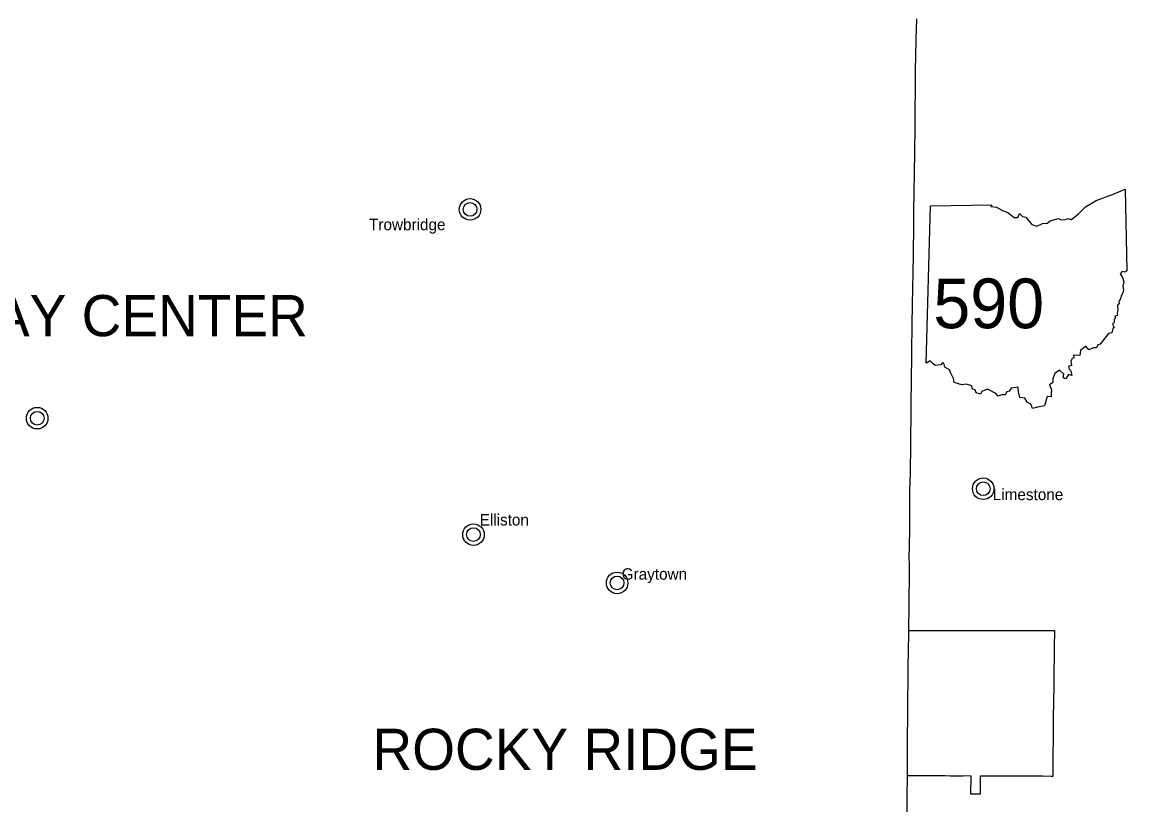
# Model space of a CAD drawing. Extents: x -82 to 873, y 0 to 440.
# Drawn here: x 144.2 to 244.9, y 182.3 to 253.6 of the extents above; entities that cross this region are included whole.
import ezdxf

# ---------------------------------------------------------------- set-up
doc = ezdxf.new("R2010")
doc.units = 0
for name, color, linetype in [('DV_X_Corp_Line', 7, 'Continuous'), ('GM_X_Corporation_Text', 7, 'Continuous'), ('GM_X_Interstate_Route', 7, 'Continuous'), ('PV_P_Text', 7, 'Continuous')]:
    doc.layers.add(name, color=color, linetype=linetype)

msp = doc.modelspace()

# ---------------------------------------------------------------- linework, layer by layer
at = {"layer": 'DV_X_Corp_Line'}
msp.add_lwpolyline([(225.04, 198.2), (226.37, 198.2), (229.03, 198.2), (230.75, 198.2), (231.37, 198.2), (231.68, 198.2), (232.06, 198.2), (233.21, 198.2), (234.89, 198.21), (235.92, 198.2), (236.53, 198.2), (237.14, 198.2), (238.31, 198.21), (238.31, 197.85), (238.3, 196.99), (238.28, 195.43), (238.27, 194.82), (238.26, 193.92), (238.25, 192.81), (238.24, 192.05), (238.23, 191.59), (238.22, 191.41), (238.21, 190.59), (238.2, 189.9), (238.19, 188.67), (238.18, 188.05), (238.17, 187.15), (238.15, 185.51), (238.15, 184.91), (238, 184.91), (237.23, 184.92), (236.53, 184.92), (234.35, 184.92), (232.84, 184.93), (232.22, 184.93), (231.55, 184.94), (231.53, 183.29), (230.69, 183.29), (230.72, 184.94), (230.41, 184.95), (230, 184.94), (229.71, 184.94), (229.26, 184.94), (228.8, 184.94), (228.35, 184.95), (227.12, 184.95), (226.01, 184.95), (224.91, 184.95), (224.91, 185.27), (224.92, 187.15), (224.93, 188.26), (224.93, 188.76), (224.93, 188.88), (224.94, 189.9), (224.94, 190.23), (224.94, 190.68), (224.95, 191.17), (224.95, 191.6), (224.95, 191.95), (224.96, 192.44), (224.97, 193.06), (224.98, 193.63), (224.99, 194.78), (224.99, 195.27), (225, 195.93), (225.02, 196.51), (225.04, 197.78)], close=True, dxfattribs=at)
for centre, radius in [((185.05, 236.58), 0.982), ((185.05, 236.58), 0.623), ((145.59, 217.55), 0.982), ((145.59, 217.55), 0.623), ((231.82, 211.12), 0.982), ((231.82, 211.12), 0.623), ((185.36, 206.94), 0.982), ((185.36, 206.94), 0.623), ((198.45, 202.54), 0.982), ((198.45, 202.54), 0.623)]:
    msp.add_circle(centre, radius, dxfattribs=at)
at = {"layer": 'GM_X_Interstate_Route'}
for points in [[(225.14, 210.28), (225.14, 210.58), (225.14, 211.03), (225.16, 211.69), (225.18, 212.59), (225.19, 213.29), (225.21, 214.4), (225.22, 215.01), (225.23, 215.38), (225.23, 215.75), (225.25, 217.85), (225.26, 218.26), (225.26, 218.96), (225.26, 219.61), (225.27, 220.27), (225.27, 221.21), (225.27, 221.75), (225.28, 221.95), (225.31, 222.36), (225.32, 222.61), (225.32, 223.22), (225.32, 223.72), (225.32, 224.29), (225.33, 225.4), (225.34, 226.18), (225.35, 226.63), (225.36, 227.33), (225.38, 228.07), (225.39, 229.22), (225.41, 229.83), (225.42, 230.37), (225.42, 230.73), (225.44, 231.39), (225.44, 231.43), (225.45, 231.84), (225.45, 232.25), (225.47, 233.16), (225.49, 234.47), (225.5, 235.13), (225.51, 236.11), (225.51, 236.64), (225.53, 238), (225.54, 238.74), (225.55, 239.27), (225.57, 240.34), (225.59, 241.28), (225.59, 241.59), (225.6, 242.6), (225.61, 243.29), (225.61, 243.95), (225.61, 244.65), (225.62, 245.24), (225.62, 245.35), (225.63, 245.84), (225.65, 247.24), (225.65, 248.18), (225.66, 248.75), (225.66, 249.2), (225.66, 249.57), (225.68, 250.31), (225.69, 250.93), (225.71, 251.67), (225.72, 252.24), (225.74, 252.94), (225.77, 253.96)], [(225.04, 198.2), (225.06, 200.39), (225.07, 200.8), (225.08, 201.75), (225.09, 202.33), (225.09, 202.42), (225.09, 203.19), (225.09, 204.34), (225.08, 204.75), (225.1, 205.98), (225.12, 207.37), (225.12, 207.7), (225.13, 208.12), (225.14, 209.52), (225.14, 210.28)], [(224.91, 184.95), (224.91, 185.27), (224.92, 187.15), (224.93, 188.26), (224.93, 188.76), (224.93, 188.88), (224.94, 189.9), (224.94, 190.23), (224.94, 190.68), (224.95, 191.17), (224.95, 191.6), (224.95, 191.95), (224.96, 192.44), (224.97, 193.06), (224.98, 193.63), (224.99, 194.78), (224.99, 195.27), (225, 195.93), (225.02, 196.51), (225.04, 197.78), (225.04, 198.2)], [(224.86, 178.3), (224.87, 178.45), (224.88, 179.15), (224.89, 179.61), (224.88, 180.72), (224.88, 181.09), (224.89, 181.7), (224.9, 182.94), (224.9, 183.63), (224.91, 184.37), (224.91, 184.95)]]:
    msp.add_lwpolyline(points, dxfattribs=at)
at = {"layer": 'PV_P_Text'}
msp.add_line((226.61, 222.55), (227.01, 236.91), dxfattribs=at)
msp.add_line((226.61, 222.55), (227.01, 236.91), dxfattribs=at)
for points in [[(227.01, 236.91), (232.59, 237), (232.5, 236.83), (233.03, 236.79), (233.59, 236.49), (234.06, 236.29), (234.64, 235.84), (234.98, 235.84), (235.13, 236.22), (235.39, 235.93), (235.71, 235.88), (236.25, 235.19), (236.7, 235.04), (237.23, 235.28), (237.64, 235.31), (237.93, 235.55), (238.69, 235.75), (238.91, 235.63), (239.31, 235.65), (239.52, 235.74), (239.87, 235.66), (240.49, 236.18), (241.13, 236.8), (242.11, 237.38), (243.59, 237.93), (244.75, 238.42), (244.92, 230.97)], [(227.01, 236.91), (232.59, 237), (232.5, 236.83), (233.03, 236.79), (233.59, 236.49), (234.06, 236.29), (234.64, 235.84), (234.98, 235.84), (235.13, 236.22), (235.39, 235.93), (235.71, 235.88), (236.25, 235.19), (236.7, 235.04), (237.23, 235.28), (237.64, 235.31), (237.93, 235.55), (238.69, 235.75), (238.91, 235.63), (239.31, 235.65), (239.52, 235.74), (239.87, 235.66), (240.49, 236.18), (241.13, 236.8), (242.11, 237.38), (243.59, 237.93), (244.75, 238.42), (244.92, 230.97)], [(244.92, 230.97), (244.74, 230.86), (244.48, 230.91), (244.3, 230.7), (244.52, 230.36), (244.63, 229.99), (244.53, 229.58), (244.62, 229.25), (244.56, 228.97), (244.39, 228.69), (244.34, 228.42), (244.19, 228.14), (244.21, 227.98), (244.07, 227.86), (244.09, 227.39), (244.02, 227.14), (244.05, 226.91), (243.83, 226.85), (243.88, 226.67), (243.74, 226.53), (243.77, 226.28), (243.61, 226.13), (243.76, 225.81), (243.64, 225.71), (243.54, 225.33), (243.25, 225.26), (242.69, 224.56), (242.49, 224.3), (242.26, 224.23), (242.14, 223.96), (241.86, 223.96), (241.44, 223.78), (241.17, 224.1), (240.7, 223.71), (240.64, 223.26), (240.04, 223.28), (240.07, 223.05), (239.93, 222.98), (239.81, 222.76), (239.88, 222.35), (239.6, 222.25), (239.64, 222.02), (239.82, 221.87), (239.9, 221.43), (239.6, 221.52), (239.35, 221.14), (239.1, 221.23), (239.18, 221.55), (238.76, 221.93), (238.36, 221.62), (238.15, 221.13), (238.15, 220.8), (237.85, 220.6), (238.04, 220.14), (238, 219.81), (238.01, 219.51), (237.64, 219.52), (237.41, 218.69)], [(244.92, 230.97), (244.74, 230.86), (244.48, 230.91), (244.3, 230.7), (244.52, 230.36), (244.63, 229.99), (244.53, 229.58), (244.62, 229.25), (244.56, 228.97), (244.39, 228.69), (244.34, 228.42), (244.19, 228.14), (244.21, 227.98), (244.07, 227.86), (244.09, 227.39), (244.02, 227.14), (244.05, 226.91), (243.83, 226.85), (243.88, 226.67), (243.74, 226.53), (243.77, 226.28), (243.61, 226.13), (243.76, 225.81), (243.64, 225.71), (243.54, 225.33), (243.25, 225.26), (242.69, 224.56), (242.49, 224.3), (242.26, 224.23), (242.14, 223.96), (241.86, 223.96), (241.44, 223.78), (241.17, 224.1), (240.7, 223.71), (240.64, 223.26), (240.04, 223.28), (240.07, 223.05), (239.93, 222.98), (239.81, 222.76), (239.88, 222.35), (239.6, 222.25), (239.64, 222.02), (239.82, 221.87), (239.9, 221.43), (239.6, 221.52), (239.35, 221.14), (239.1, 221.23), (239.18, 221.55), (238.76, 221.93), (238.36, 221.62), (238.15, 221.13), (238.15, 220.8), (237.85, 220.6), (238.04, 220.14), (238, 219.81), (238.01, 219.51), (237.64, 219.52), (237.41, 218.69)], [(237.41, 218.69), (236.76, 218.54), (236.31, 218.44), (236.15, 218.82), (235.83, 219.01), (235.62, 219.39), (235.15, 219.44), (235.04, 219.96), (234.99, 220.38), (234.36, 220.28), (234.18, 220.02), (233.96, 219.95), (233.83, 219.69), (233.52, 219.67), (233.19, 219.55), (232.98, 219.8), (232.44, 220.06), (232.2, 220.19), (231.69, 219.98), (231.58, 219.74), (231.18, 219.85), (231.08, 220.12), (230.84, 220.2), (230.79, 220.49), (230.26, 220.64), (229.87, 220.58), (229.16, 220.81), (229.12, 221.18), (228.88, 221.64), (228.75, 221.96), (228.31, 222.2), (228.22, 222.58), (228.08, 222.57), (227.95, 222.42), (227.45, 222.35), (227.26, 222.5), (226.98, 222.77), (226.61, 222.55)], [(237.41, 218.69), (236.76, 218.54), (236.31, 218.44), (236.15, 218.82), (235.83, 219.01), (235.62, 219.39), (235.15, 219.44), (235.04, 219.96), (234.99, 220.38), (234.36, 220.28), (234.18, 220.02), (233.96, 219.95), (233.83, 219.69), (233.52, 219.67), (233.19, 219.55), (232.98, 219.8), (232.44, 220.06), (232.2, 220.19), (231.69, 219.98), (231.58, 219.74), (231.18, 219.85), (231.08, 220.12), (230.84, 220.2), (230.79, 220.49), (230.26, 220.64), (229.87, 220.58), (229.16, 220.81), (229.12, 221.18), (228.88, 221.64), (228.75, 221.96), (228.31, 222.2), (228.22, 222.58), (228.08, 222.57), (227.95, 222.42), (227.45, 222.35), (227.26, 222.5), (226.98, 222.77), (226.61, 222.55)]]:
    msp.add_lwpolyline(points, dxfattribs=at)

# ---------------------------------------------------------------- texts
at = {"layer": 'DV_X_Corp_Line'}
for s, p in [('Trowbridge', (175.84, 234.68)), ('Limestone', (232.69, 210.08)), ('Elliston', (185.92, 207.77)), ('Graytown', (198.87, 202.83))]:
    msp.add_text(s, height=1.042, rotation=0.005, dxfattribs=at).set_placement(p)
at = {"layer": 'GM_X_Corporation_Text'}
for s, p in [('CLAY CENTER', (135.15, 225.02)), ('ROCKY RIDGE', (176.15, 185.5))]:
    msp.add_text(s, height=3.75, rotation=0.005, dxfattribs=at).set_placement(p)
at = {"layer": 'PV_P_Text'}
msp.add_text('590', height=4.528, rotation=0.005, dxfattribs=at).set_placement((227.27, 225.75))

doc.saveas('drawing.dxf')
